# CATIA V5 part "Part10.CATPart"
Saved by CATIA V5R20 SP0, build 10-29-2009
Part number: 1DIN7984616_DIN 7984 - M6 x 16 --- 16C
Revision: ANY
Definition: UNKNOWN
Nomenclature: 1DIN7984616_DIN 7984 - M6 x 16 --- 16C
Source: Unknown
Bounding box of the stored display mesh (mm): x 0 to 20, y -5 to 5, z -5 to 5
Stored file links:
  C:\Users\Utente\Desktop\IO LAVORO\3D X SITO CF\CUMSA\3D files PW\pw101430\pw101430_injection\Part10.CATPart
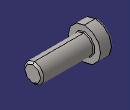
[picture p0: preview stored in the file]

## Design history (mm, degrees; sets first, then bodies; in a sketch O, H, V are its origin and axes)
Body1 "Hex" (main body)
  Solid1: solid without history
